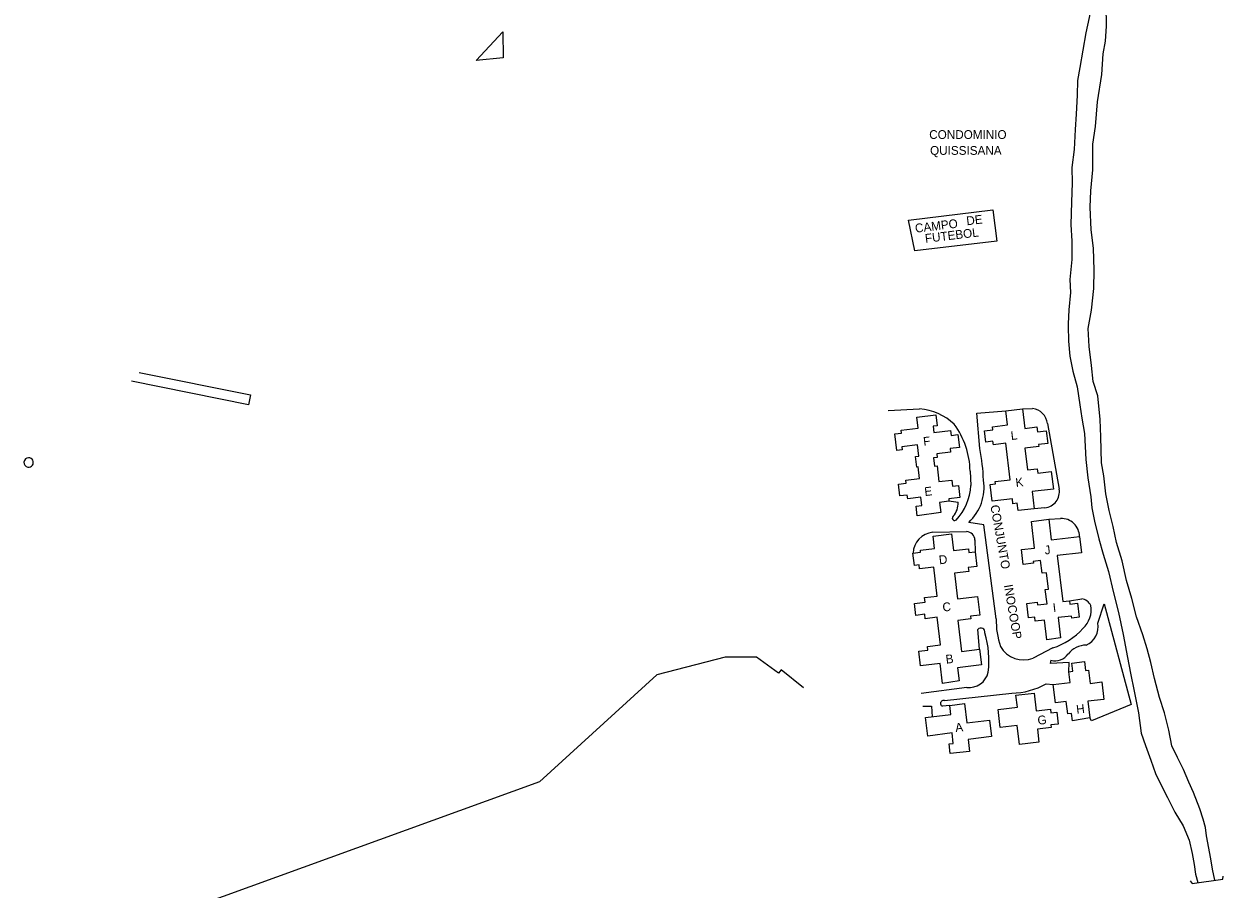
# Model space of a CAD drawing. Extents: x 325899 to 363134, y 7578590 to 7592502.
# Drawn here: x 338125 to 338673, y 7588098 to 7588493 of the extents above; entities that cross this region are included whole.
import ezdxf

# ---------------------------------------------------------------- set-up
doc = ezdxf.new("R2010")
doc.units = 0
for name, color, linetype in [('EDIFEXISTENT', 7, 'Continuous'), ('EDIFIDENTIF', 7, 'Continuous'), ('EDIFOBRAEXIS', 7, 'Continuous')]:
    doc.layers.add(name, color=color, linetype=linetype)

msp = doc.modelspace()

# ---------------------------------------------------------------- linework, layer by layer
at = {"layer": 'EDIFEXISTENT'}
for p, q in [((338529.39, 7588403.79), (338568.04, 7588408.4)), ((338568.04, 7588408.4), (338569.74, 7588394.17)), ((338532.31, 7588389.7), (338529.39, 7588403.79)), ((338569.74, 7588394.17), (338532.31, 7588389.7)), ((338573.98, 7588316.63), (338581.52, 7588317.53)), ((338581.52, 7588317.53), (338582.58, 7588308.64)), ((338533.25, 7588313.77), (338542, 7588314.82)), ((338533.85, 7588308.79), (338533.25, 7588313.77)), ((338542, 7588314.82), (338542.59, 7588309.85)), ((338574.75, 7588310.18), (338573.98, 7588316.63)), ((338526.15, 7588307.87), (338533.85, 7588308.79)), ((338526.31, 7588306.49), (338526.15, 7588307.87)), ((338542.59, 7588309.85), (338540.71, 7588309.63)), ((338540.71, 7588309.63), (338541.05, 7588306.77)), ((338541.05, 7588306.77), (338548.61, 7588307.67)), ((338548.61, 7588307.67), (338548.87, 7588305.44)), ((338564.17, 7588307.53), (338568.04, 7588307.99)), ((338564.8, 7588302.33), (338564.17, 7588307.53)), ((338567.87, 7588309.36), (338574.75, 7588310.18)), ((338568.04, 7588307.99), (338567.87, 7588309.36)), ((338582.58, 7588308.64), (338588.14, 7588309.3)), ((338588.14, 7588309.3), (338588.41, 7588307.03)), ((338588.41, 7588307.03), (338592.42, 7588307.51)), ((338592.42, 7588307.51), (338593.11, 7588301.74)), ((338523.15, 7588306.11), (338526.31, 7588306.49)), ((338524.06, 7588298.47), (338523.15, 7588306.11)), ((338533.6, 7588301.09), (338526.4, 7588300.24)), ((338534.21, 7588295.91), (338533.6, 7588301.09)), ((338548.87, 7588305.44), (338552.02, 7588305.82)), ((338552.02, 7588305.82), (338552.72, 7588299.96)), ((338568.06, 7588302.72), (338564.8, 7588302.33)), ((338568.25, 7588301.19), (338568.06, 7588302.72)), ((338573.98, 7588301.87), (338568.25, 7588301.19)), ((338575.97, 7588285.19), (338573.98, 7588301.87)), ((338593.11, 7588301.74), (338588.87, 7588301.23)), ((338588.87, 7588301.23), (338588.98, 7588300.33)), ((338526.57, 7588298.77), (338524.06, 7588298.47)), ((338526.4, 7588300.24), (338526.57, 7588298.77)), ((338532.62, 7588295.72), (338534.21, 7588295.91)), ((338533.19, 7588290.94), (338532.62, 7588295.72)), ((338548.68, 7588297.72), (338542.41, 7588296.97)), ((338542.41, 7588296.97), (338542.6, 7588295.4)), ((338552.72, 7588299.96), (338548.47, 7588299.46)), ((338548.47, 7588299.46), (338548.68, 7588297.72)), ((338588.98, 7588300.33), (338582.6, 7588299.57)), ((338582.6, 7588299.57), (338583.78, 7588289.68)), ((338533.88, 7588291.03), (338533.19, 7588290.94)), ((338534.52, 7588285.69), (338533.88, 7588291.03)), ((338542.6, 7588295.4), (338540.9, 7588295.2)), ((338540.9, 7588295.2), (338541.35, 7588291.39)), ((338541.35, 7588291.39), (338542.53, 7588291.53)), ((338542.53, 7588291.53), (338543.38, 7588284.36)), ((338583.78, 7588289.68), (338588.29, 7588290.21)), ((338588.29, 7588290.21), (338588.53, 7588288.2)), ((338528.18, 7588284.93), (338534.52, 7588285.69)), ((338528.34, 7588283.61), (338528.18, 7588284.93)), ((338543.38, 7588284.36), (338549.22, 7588285.06)), ((338549.22, 7588285.06), (338549.56, 7588282.26)), ((338569.02, 7588284.36), (338575.97, 7588285.19)), ((338588.53, 7588288.2), (338594.69, 7588288.94)), ((338594.69, 7588288.94), (338595.64, 7588280.95)), ((338524.88, 7588283.19), (338528.34, 7588283.61)), ((338525.53, 7588277.79), (338524.88, 7588283.19)), ((338549.56, 7588282.26), (338552.3, 7588282.58)), ((338552.3, 7588282.58), (338552.96, 7588277.05)), ((338566.69, 7588283.07), (338569.14, 7588283.36)), ((338567.61, 7588275.32), (338566.69, 7588283.07)), ((338569.14, 7588283.36), (338569.02, 7588284.36)), ((338595.64, 7588280.95), (338585.9, 7588279.79)), ((338585.9, 7588279.79), (338586.85, 7588271.84)), ((338528.9, 7588278.19), (338525.53, 7588277.79)), ((338529.11, 7588276.47), (338528.9, 7588278.19)), ((338535.03, 7588277.18), (338529.11, 7588276.47)), ((338535.47, 7588273.48), (338535.03, 7588277.18)), ((338547.94, 7588275.35), (338543.64, 7588274.83)), ((338543.64, 7588274.83), (338544.2, 7588270.15)), ((338552.96, 7588277.05), (338547.81, 7588276.43)), ((338547.81, 7588276.43), (338547.94, 7588275.35)), ((338576.93, 7588276.43), (338567.61, 7588275.32)), ((338577.2, 7588274.21), (338576.93, 7588276.43)), ((338579.14, 7588274.44), (338577.2, 7588274.21)), ((338579.54, 7588271.06), (338579.14, 7588274.44)), ((338532.9, 7588273.17), (338535.47, 7588273.48)), ((338533.44, 7588268.64), (338532.9, 7588273.17)), ((338544.2, 7588270.15), (338533.44, 7588268.64)), ((338586.85, 7588271.84), (338579.54, 7588271.06)), ((338585.63, 7588266.15), (338593.59, 7588267.1)), ((338587.08, 7588253.99), (338585.63, 7588266.15)), ((338593.59, 7588267.1), (338594.71, 7588257.72)), ((338540.67, 7588259.45), (338549.08, 7588260.45)), ((338541.34, 7588253.84), (338540.67, 7588259.45)), ((338549.08, 7588260.45), (338549.99, 7588252.81)), ((338594.71, 7588257.72), (338607.6, 7588259.26)), ((338607.6, 7588259.26), (338608.48, 7588251.86)), ((338531.5, 7588251.67), (338534.99, 7588252.08)), ((338534.87, 7588253.07), (338541.34, 7588253.84)), ((338534.99, 7588252.08), (338534.87, 7588253.07)), ((338549.99, 7588252.81), (338556.81, 7588253.63)), ((338556.81, 7588253.63), (338557.02, 7588251.91)), ((338557.02, 7588251.91), (338559.86, 7588252.25)), ((338559.86, 7588252.25), (338560.66, 7588245.58)), ((338581.01, 7588253.26), (338587.08, 7588253.99)), ((338581.82, 7588246.53), (338581.01, 7588253.26)), ((338608.48, 7588251.86), (338597.4, 7588250.53)), ((338532.17, 7588246.08), (338531.5, 7588251.67)), ((338534.25, 7588246.33), (338532.17, 7588246.08)), ((338534.47, 7588244.49), (338534.25, 7588246.33)), ((338586.58, 7588247.1), (338581.82, 7588246.53)), ((338589.79, 7588248.24), (338586.49, 7588247.85)), ((338586.49, 7588247.85), (338586.58, 7588247.1)), ((338590.48, 7588242.49), (338589.79, 7588248.24)), ((338597.4, 7588250.53), (338599.9, 7588229.55)), ((338541.02, 7588245.28), (338534.47, 7588244.49)), ((338542.6, 7588232.03), (338541.02, 7588245.28)), ((338556.97, 7588243.31), (338550.48, 7588242.54)), ((338550.48, 7588242.54), (338551.89, 7588230.77)), ((338560.66, 7588245.58), (338556.75, 7588245.11)), ((338556.75, 7588245.11), (338556.97, 7588243.31)), ((338592.53, 7588242.73), (338590.48, 7588242.49)), ((338593.42, 7588235.26), (338592.53, 7588242.73)), ((338591.96, 7588235.08), (338593.42, 7588235.26)), ((338536.8, 7588231.34), (338542.6, 7588232.03)), ((338537.05, 7588229.24), (338536.8, 7588231.34)), ((338551.89, 7588230.77), (338561.05, 7588231.87)), ((338561.05, 7588231.87), (338562.07, 7588223.36)), ((338592.74, 7588228.56), (338591.96, 7588235.08)), ((338599.9, 7588229.55), (338602.96, 7588229.91)), ((338602.96, 7588229.91), (338603.15, 7588228.32)), ((338532.21, 7588228.67), (338537.05, 7588229.24)), ((338532.86, 7588223.25), (338532.21, 7588228.67)), ((338583.54, 7588228.71), (338588.28, 7588229.28)), ((338584.32, 7588222.16), (338583.54, 7588228.71)), ((338588.28, 7588229.28), (338588.42, 7588228.04)), ((338588.42, 7588228.04), (338592.74, 7588228.56)), ((338603.15, 7588228.32), (338606.61, 7588228.74)), ((338606.61, 7588228.74), (338607.37, 7588222.36)), ((338536.85, 7588223.72), (338532.86, 7588223.25)), ((338537.09, 7588221.71), (338536.85, 7588223.72)), ((338542.52, 7588222.35), (338537.09, 7588221.71)), ((338544.02, 7588209.73), (338542.52, 7588222.35)), ((338557.94, 7588221.65), (338551.95, 7588220.93)), ((338551.95, 7588220.93), (338553.64, 7588206.81)), ((338562.07, 7588223.36), (338557.79, 7588222.85)), ((338557.79, 7588222.85), (338557.94, 7588221.65)), ((338587.11, 7588222.49), (338584.32, 7588222.16)), ((338587.34, 7588220.61), (338587.11, 7588222.49)), ((338591.61, 7588221.12), (338587.34, 7588220.61)), ((338592.69, 7588212.02), (338591.61, 7588221.12)), ((338603.95, 7588222.92), (338597.8, 7588222.19)), ((338597.8, 7588222.19), (338598.9, 7588213)), ((338604.06, 7588221.96), (338603.95, 7588222.92)), ((338607.37, 7588222.36), (338604.06, 7588221.96)), ((338538.08, 7588209.02), (338544.02, 7588209.73)), ((338538.27, 7588207.42), (338538.08, 7588209.02)), ((338598.9, 7588213), (338592.69, 7588212.02)), ((338534.18, 7588206.93), (338538.27, 7588207.42)), ((338534.99, 7588200.18), (338534.18, 7588206.93)), ((338553.64, 7588206.81), (338561.96, 7588207.8)), ((338561.96, 7588207.8), (338562.81, 7588200.61)), ((338543.93, 7588201.25), (338534.99, 7588200.18)), ((338545.01, 7588192.18), (338543.93, 7588201.25)), ((338562.81, 7588200.61), (338551.83, 7588199.3)), ((338551.83, 7588199.3), (338552.55, 7588193.28)), ((338602.77, 7588197.49), (338604.59, 7588197.71)), ((338603.35, 7588192.63), (338602.77, 7588197.49)), ((338604.14, 7588201.44), (338609.86, 7588202.13)), ((338604.59, 7588197.71), (338604.14, 7588201.44)), ((338609.86, 7588202.13), (338610.35, 7588198.01)), ((338610.35, 7588198.01), (338611.7, 7588198.17)), ((338611.7, 7588198.17), (338612.41, 7588192.19)), ((338552.55, 7588193.28), (338545.01, 7588192.18)), ((338595.61, 7588191.71), (338603.35, 7588192.63)), ((338596.61, 7588183.3), (338595.61, 7588191.71)), ((338612.41, 7588192.19), (338617.78, 7588192.83)), ((338617.78, 7588192.83), (338618.72, 7588184.89)), ((338578.55, 7588186.77), (338586.86, 7588187.76)), ((338579.2, 7588181.31), (338578.55, 7588186.77)), ((338586.86, 7588187.76), (338587.84, 7588179.61)), ((338548.36, 7588182.14), (338555.11, 7588182.94)), ((338548.86, 7588177.97), (338548.36, 7588182.14)), ((338555.11, 7588182.94), (338556.16, 7588174.18)), ((338570.36, 7588180.26), (338579.2, 7588181.31)), ((338601.56, 7588183.89), (338596.61, 7588183.3)), ((338602.23, 7588178.25), (338601.56, 7588183.89)), ((338618.72, 7588184.89), (338611.39, 7588184.02)), ((338611.39, 7588184.02), (338612.3, 7588176.4)), ((338537.27, 7588176.59), (338548.86, 7588177.97)), ((338538.28, 7588168.12), (338537.27, 7588176.59)), ((338556.16, 7588174.18), (338566.45, 7588175.41)), ((338566.45, 7588175.41), (338567.35, 7588167.85)), ((338571.33, 7588172.08), (338570.36, 7588180.26)), ((338587.84, 7588179.61), (338594.31, 7588180.39)), ((338594.31, 7588180.39), (338594.51, 7588178.69)), ((338594.51, 7588178.69), (338597.18, 7588179.01)), ((338597.18, 7588179.01), (338597.83, 7588173.56)), ((338603.97, 7588178.46), (338602.23, 7588178.25)), ((338604.37, 7588175.11), (338603.97, 7588178.46)), ((338612.3, 7588176.4), (338604.37, 7588175.11)), ((338549.33, 7588169.57), (338538.28, 7588168.12)), ((338549.9, 7588164.75), (338549.33, 7588169.57)), ((338579.06, 7588172.99), (338571.33, 7588172.08)), ((338580.1, 7588164.23), (338579.06, 7588172.99)), ((338594.67, 7588172.01), (338588.35, 7588171.26)), ((338588.35, 7588171.26), (338589.06, 7588165.3)), ((338597.83, 7588173.56), (338594.54, 7588173.17)), ((338594.54, 7588173.17), (338594.67, 7588172.01)), ((338547.97, 7588164.52), (338549.9, 7588164.75)), ((338548.5, 7588160.08), (338547.97, 7588164.52)), ((338567.35, 7588167.85), (338556.69, 7588166.58)), ((338556.69, 7588166.58), (338557.34, 7588161.13)), ((338589.06, 7588165.3), (338580.1, 7588164.23)), ((338557.34, 7588161.13), (338548.5, 7588160.08)), ((338673.04, 7588102.71), (338673.18, 7588104.08)), ((338658.12, 7588101.98), (338659.14, 7588100.8)), ((338659.14, 7588100.8), (338673.04, 7588102.71))]:
    msp.add_line(p, q, dxfattribs=at)
at = {"layer": 'EDIFOBRAEXIS'}
for points in [[(338613.28, 7588501.91), (338610.49, 7588489.31), (338607.73, 7588473.5), (338606.63, 7588467.49), (338606.59, 7588460.83), (338606.12, 7588452.16), (338605.59, 7588445.16), (338605.08, 7588436.06), (338604.03, 7588427.77), (338604.26, 7588420.8), (338603.93, 7588411.91), (338603.6, 7588401.77), (338604.15, 7588394.1), (338604.08, 7588385.71), (338603.19, 7588376.61), (338603.54, 7588370.69), (338602.69, 7588362.75), (338602.47, 7588356.36), (338602.47, 7588355.5), (338602.53, 7588348.51), (338603.14, 7588341.62), (338604.48, 7588334.72), (338606.47, 7588327.59), (338607.72, 7588319.39), (338608.71, 7588313.32), (338609.85, 7588306.36), (338610.42, 7588294.48), (338611.45, 7588286.05), (338612.76, 7588277.35), (338613.18, 7588272.36), (338614.37, 7588266.27), (338616.36, 7588258.25), (338618.47, 7588251.15), (338620.89, 7588243.21), (338623.09, 7588233.6), (338625.34, 7588224.5), (338627.52, 7588214.46), (338629.55, 7588204.01), (338630.93, 7588196.83), (338632.59, 7588188.66), (338634.57, 7588178.71), (338635.8, 7588169.43), (338637.75, 7588163.82), (338640.23, 7588157.12), (338642.33, 7588150.98), (338644.5, 7588146.54), (338647.87, 7588140.01), (338651.21, 7588133.37), (338654.96, 7588127.19), (338657.65, 7588120.63), (338659.14, 7588114.53), (338660.06, 7588109.47), (338660.61, 7588104.97), (338661.6, 7588101.22)], [(338669.42, 7588102.23), (338668.42, 7588107.28), (338667.59, 7588112.09), (338665.61, 7588122.56), (338665.13, 7588126.31), (338664.08, 7588130.15), (338662.55, 7588134.83), (338659.75, 7588142.4), (338657.49, 7588147.12), (338655.06, 7588152.88), (338652.31, 7588158.26), (338649.76, 7588163.63), (338648.38, 7588170.74), (338646.42, 7588178.68), (338644.11, 7588185.76), (338641.92, 7588194.33), (338640.16, 7588201.74), (338638.59, 7588207.88), (338636.49, 7588214.3), (338633.66, 7588222.54), (338631.47, 7588231.01), (338629.05, 7588239.09), (338627.03, 7588248.07), (338624.43, 7588256.59), (338622.95, 7588263.9), (338621.22, 7588271.16), (338619.62, 7588278.7), (338618.64, 7588287), (338617.68, 7588292.94), (338617.29, 7588304.85), (338616.97, 7588312.75), (338615.92, 7588323.46), (338613.82, 7588330.05), (338613, 7588337.39), (338612, 7588346.08), (338611.48, 7588354.28), (338613.06, 7588362.65), (338614.07, 7588372.52), (338614.36, 7588380.93), (338614.03, 7588390.88), (338612.97, 7588399.29), (338612.41, 7588409.7), (338612.76, 7588417.12), (338613.69, 7588426.71), (338613.68, 7588438.44), (338614.86, 7588446.55), (338615.81, 7588457.73), (338617.74, 7588470.21), (338618.34, 7588479.69), (338619.52, 7588485.48), (338619.87, 7588492.3), (338619.72, 7588501.91)], [(338331.9, 7588476.61), (338344.12, 7588489.77), (338344.25, 7588477.81), (338331.9, 7588476.61)], [(338177.84, 7588334.22), (338228.72, 7588323.91)], [(338228.72, 7588323.91), (338227.81, 7588319.36), (338174.29, 7588330.2)], [(338520.18, 7588316.8), (338534.48, 7588317.56)], [(338562.08, 7588299.4), (338560.7, 7588315.56), (338573.98, 7588316.63), (338581.52, 7588317.53), (338586.17, 7588317.77)], [(338592.97, 7588310.86), (338598.33, 7588280.93)], [(338557.6, 7588289.13), (338557.96, 7588282.54)], [(338552.19, 7588274.86), (338547.94, 7588275.35)], [(338591.81, 7588272.34), (338586.85, 7588271.84)], [(338569.52, 7588221.69), (338563.91, 7588264.51), (338556.95, 7588265.72)], [(338593.59, 7588267.1), (338598.95, 7588267.48)], [(338540.51, 7588261.18), (338556, 7588261.53)], [(338559.81, 7588257.66), (338559.86, 7588252.25)], [(338602.96, 7588229.91), (338608.64, 7588230.82)], [(338615.98, 7588219.72), (338618.83, 7588228.49), (338631.16, 7588182.5), (338613.14, 7588175.03), (338612.3, 7588176.4)], [(338561.96, 7588207.8), (338561.15, 7588216.78)], [(338595.39, 7588208.38), (338586.45, 7588203.72)], [(338481.39, 7588190.13), (338471.26, 7588198.35), (338470.08, 7588196.82), (338459.91, 7588204.12), (338445.71, 7588204.19), (338414.48, 7588196.06), (338360.86, 7588147.14), (338204.04, 7588090.5), (338158.53, 7588029.1)], [(338602.77, 7588197.49), (338602.87, 7588201.72), (338594.35, 7588201.2), (338594.57, 7588202.75)], [(338592.42, 7588192.01), (338595.61, 7588191.71)], [(338556.03, 7588190.35), (338535.19, 7588187.62)], [(338545.91, 7588184.31), (338576.64, 7588187.72)], [(338535.95, 7588181.74), (338539.95, 7588181.7), (338540.27, 7588176.96)], [(338548.36, 7588182.14), (338545, 7588181.74)]]:
    msp.add_lwpolyline(points, dxfattribs=at)
for centre, radius, start, end in [((338532.59, 7588291.89), 25.74, 46.3417, 85.7805), ((338584.94, 7588309.77), 8.1, 7.7275, 81.2796), ((338520.69, 7588288.55), 36.91, 0.8968, 36.5203), ((338465.72, 7588281.34), 98.04, 2.1176, 10.6148), ((338127.36, 7588293.09), 2.14, 90.999, 258.8725), ((338127.35, 7588293.09), 2.14, 259.3289, 90.5426), ((338542.43, 7588281.61), 21.53, 312.423, 8.9622), ((338532.92, 7588283.97), 25.08, 316.7517, 356.7184), ((338591, 7588279.73), 7.43, 276.2672, 9.3447), ((338542.36, 7588274.78), 9.83, 320.164, 0.4901), ((338550.52, 7588267.62), 1.06, 125.4248, 308.9541), ((338599.32, 7588259.21), 8.28, 0.3233, 92.6084), ((338541.53, 7588251.2), 10.04, 95.8303, 177.3005), ((338555.65, 7588257.38), 4.16, 3.8068, 85.2157), ((338607.78, 7588225.42), 5.47, 25.3165, 80.9457), ((338601.8, 7588225.66), 11.13, 311.2336, 10.9015), ((338607.22, 7588220.92), 37.71, 178.8389, 198.4306), ((338606.96, 7588218.03), 9.18, 293.9637, 10.6245), ((338562.56, 7588215.62), 1.83, 347.6394, 140.8736), ((338523.52, 7588202.68), 42.71, 352.6867, 17.0856), ((338585.71, 7588238.38), 31.52, 287.881, 318.0018), ((338582.01, 7588215.07), 12.18, 209.8652, 291.3472), ((338610.7, 7588199.07), 10.57, 90.0429, 141.8916), ((338596.4, 7588209.84), 7.33, 255.4835, 324.6199), ((338557.12, 7588199.28), 9, 263.0468, 346.9208), ((338576.18, 7588220.65), 32.94, 270.8053, 299.5589), ((338545.42, 7588183.04), 1.36, 68.6767, 251.9973)]:
    msp.add_arc(centre, radius, start, end, dxfattribs=at)

# ---------------------------------------------------------------- texts
at = {"layer": 'EDIFIDENTIF'}
for s, p in [('CONDOMINIO', (338538.91, 7588440.83)), ('QUISSISANA', (338539.3, 7588433.57))]:
    msp.add_text(s, height=4, dxfattribs=at).set_placement(p)
for s, rotation, p in [('DE', 6.8011, (338556.12, 7588401.37)), ('CAMPO', 6.8011, (338532.67, 7588398)), ('FUTEBOL', 6.8011, (338537.21, 7588393.37)), ('L', 6.8011, (338576.4, 7588303.3)), ('F', 6.8011, (338536.4, 7588300.62)), ('K', 6.8011, (338578.59, 7588281.85)), ('E', 6.8011, (338536.94, 7588277.7)), ('CONJUNTO', 280.1225, (338566.83, 7588273.34)), ('J', 6.8011, (338591.86, 7588250.99)), ('D', 6.8011, (338543.56, 7588246.54)), ('INOCOOP', 279.8172, (338573.03, 7588237.01)), ('C', 6.8011, (338545.22, 7588224.91)), ('I', 6.8011, (338595.63, 7588224.72)), ('B', 6.8011, (338546.66, 7588201.16)), ('H', 6.8011, (338606.33, 7588178.28)), ('G', 6.8011, (338588.66, 7588173.23)), ('A', 6.8011, (338551.01, 7588169.93))]:
    msp.add_text(s, height=4, rotation=rotation, dxfattribs=at).set_placement(p)

doc.saveas('drawing.dxf')
